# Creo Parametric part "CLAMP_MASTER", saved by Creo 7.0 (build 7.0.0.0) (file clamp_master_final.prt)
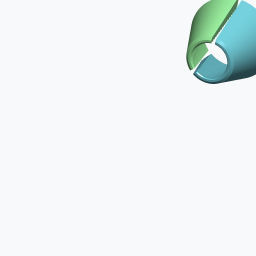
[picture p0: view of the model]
Units: millimeter Kilogram Sec (mmKs); MM, KILOGRAM, SECS
Materials in the file: PP

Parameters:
  PTC_MATERIAL_NAME = "PP"
  GRANTA_DATALINK_VERSION = "5"
  GRANTA_DATABASE_KEY = "Granta_Typical_Materials"
  GRANTA_IDENTITY_GUID = "ff860c73-d74d-48d2-a9b6-5ced973d81f3"
  GRANTA_VERSION_GUID = "0e93ee24-01f8-4558-b835-9833d1fcc101"
  GRANTA_MODEL_REFERENCE = "00000000-0000-0000-0000-000000000000"

Other parameters: PIECE_NUM

Created from: XX_INLBS_PART_SOLID_ABS.PRT

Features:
  1. datum plane "RIGHT"
  2. datum plane "TOP"
  3. datum plane "FRONT"
  4. coordinate system
  5. sketch "Sketch 1"
  6. sketch "Sketch 2", "A_3"
  7. sketch "Sketch 3"
  8. revolve "Revolve 1"
  9. chamfer "Chamfer 1"
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
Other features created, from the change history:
  group "COPIED_GROUP"
  cut "Volume Helical Sweep 1" (2 times)
  extruded cut "Extrude 1" (2 times)
  feature "Split Out Body 1" (2 times)
  chamfer "Chamfer 2" (4 times)
  feature "Split Body 1" (2 times)

Other named items: PIECE1, PIECE2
